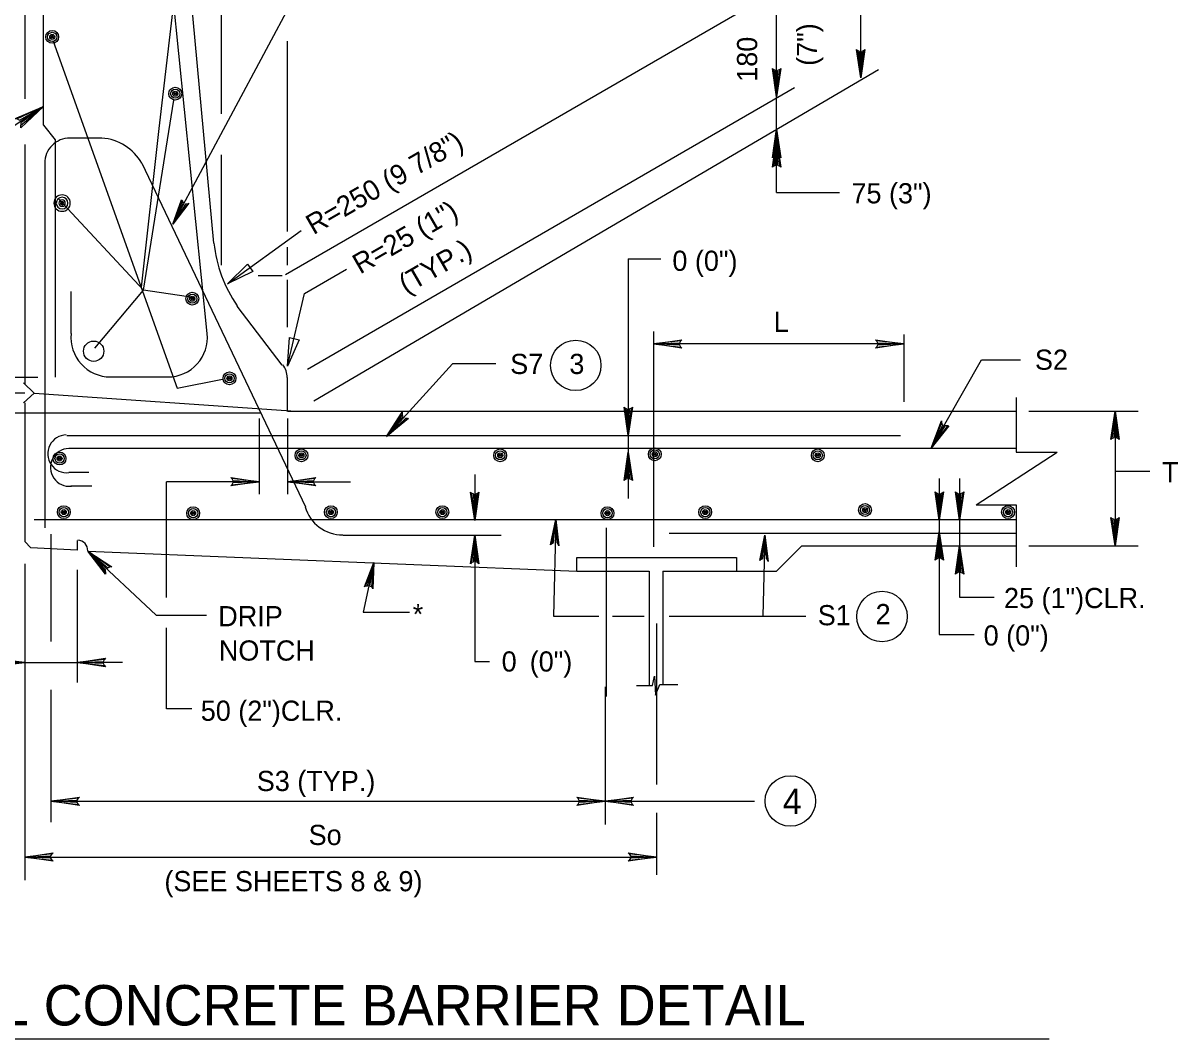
# Model space of a CAD drawing. Extents: x 652000 to 652262, y 303155 to 303399.
# Drawn here: x 652090.8 to 652262.4, y 303155 to 303306 of the extents above; entities that cross this region are included whole.
import ezdxf

# ---------------------------------------------------------------- set-up
doc = ezdxf.new("R2010")
doc.units = 0
doc.layers.add('2', color=7, linetype='Continuous')

msp = doc.modelspace()

# ---------------------------------------------------------------- linework, layer by layer
at = {"layer": '2'}
for p, q in [((652215.29, 303297.83), (652215.29, 303383.14)), ((652120.29, 303292.52), (652120.29, 303373.21)), ((652091.07, 303332.36), (652091.07, 303294.75)), ((652119.19, 303273.3), (652113.72, 303332.21)), ((652093.88, 303290.8), (652093.88, 303328.46)), ((652118.18, 303259.85), (652111.22, 303328.77)), ((652111.07, 303290.33), (652114.82, 303322.36)), ((652113.1, 303276.11), (652133.25, 303313.77)), ((652129.82, 303268.61), (652205.44, 303312.36)), ((652202.79, 303295.02), (652202.79, 303310.8)), ((652095.29, 303303.3), (652113.72, 303251.74)), ((652130.13, 303275.02), (652130.13, 303303.3)), ((652134.04, 303249.86), (652217.94, 303299.08)), ((652133.1, 303254.55), (652205.44, 303296.42)), ((652108.72, 303266.27), (652113.25, 303294.55)), ((652202.79, 303290.2), (652202.79, 303295.02)), ((652093.88, 303293.61), (652084.19, 303287.21)), ((652093.88, 303290.8), (652095.6, 303288.61)), ((652108.41, 303266.74), (652111.07, 303290.33)), ((652202.79, 303280.8), (652202.79, 303290.2)), ((652095.6, 303288.61), (652095.6, 303253.36)), ((652102.54, 303288.9), (652097.79, 303288.9)), ((652091.07, 303287.93), (652091.07, 303284.39)), ((652094.04, 303285.15), (652094.04, 303230.96)), ((652108.48, 303285.15), (652132.79, 303234.08)), ((652120.29, 303270.02), (652120.29, 303286.42)), ((652091.07, 303284.39), (652091.07, 303252.36)), ((652202.79, 303280.8), (652212.16, 303280.8)), ((652108.72, 303266.27), (652096.07, 303279.86)), ((652121.22, 303267.21), (652132.16, 303275.17)), ((652130.13, 303270.02), (652130.13, 303272.67)), ((652180.75, 303270.96), (652185.6, 303270.96)), ((652180.75, 303270.96), (652180.75, 303244.71)), ((652125.75, 303268.46), (652129.35, 303268.46)), ((652132.63, 303265.8), (652138.88, 303269.39)), ((652101.47, 303257.66), (652108.72, 303266.27)), ((652116.38, 303265.17), (652108.72, 303266.27)), ((652130.13, 303260.8), (652130.13, 303267.83)), ((652097.97, 303259.85), (652097.97, 303266.1)), ((652130.13, 303255.02), (652132.63, 303265.8)), ((652129.35, 303255.17), (652122.63, 303263.92)), ((652184.5, 303260.17), (652184.5, 303228.14)), ((652221.69, 303259.71), (652221.69, 303249.71)), ((652221.69, 303258.3), (652184.5, 303258.3)), ((652225.75, 303242.83), (652233.25, 303255.96)), ((652233.25, 303255.96), (652239.04, 303255.96)), ((652154.66, 303255.33), (652144.82, 303244.55)), ((652161.07, 303255.33), (652154.66, 303255.33)), ((652093.02, 303253.3), (652085.44, 303253.3)), ((652090.91, 303252.52), (652092.47, 303250.96)), ((652112.32, 303253.38), (652103.72, 303253.38)), ((652113.72, 303251.74), (652120.45, 303253.07)), ((652130.13, 303248.3), (652130.13, 303253.3)), ((652130.13, 303248.3), (652130.13, 303252.67)), ((652091.07, 303250.96), (652054.69, 303250.96)), ((652090.91, 303249.55), (652092.47, 303250.96)), ((652092.47, 303250.96), (652131.38, 303248.3)), ((652091.07, 303249.55), (652091.07, 303228.92)), ((652238.41, 303250.33), (652238.41, 303242.21)), ((652126.22, 303247.99), (652088.88, 303247.99)), ((652130.13, 303248.3), (652238.41, 303248.3)), ((652240.29, 303248.3), (652256.54, 303248.3)), ((652253.1, 303248.3), (652253.1, 303228.3)), ((652125.91, 303247.21), (652125.91, 303235.96)), ((652130.13, 303247.21), (652130.13, 303235.96)), ((652097.32, 303244.71), (652221.22, 303244.71)), ((652180.75, 303244.71), (652180.75, 303242.21)), ((652097.63, 303242.83), (652238.41, 303242.83)), ((652180.75, 303242.21), (652180.75, 303235.33)), ((652232.47, 303234.39), (652244.5, 303242.21)), ((652238.41, 303242.21), (652244.5, 303242.21)), ((652097.63, 303239.24), (652100.6, 303239.24)), ((652157.94, 303238.92), (652157.94, 303232.05)), ((652253.1, 303239.39), (652258.25, 303239.39)), ((652097.94, 303237.21), (652101.07, 303237.21)), ((652125.91, 303237.83), (652112.16, 303237.83)), ((652112.16, 303220.64), (652112.16, 303237.83)), ((652130.13, 303237.83), (652139.5, 303237.83)), ((652226.97, 303238.3), (652226.97, 303231.74)), ((652229.99, 303238.3), (652229.99, 303231.74)), ((652232.47, 303234.39), (652238.41, 303234.39)), ((652238.41, 303234.39), (652238.41, 303225.17)), ((652092.5, 303232.21), (652238.41, 303232.21)), ((652169.97, 303232.21), (652169.66, 303217.83)), ((652177.47, 303230.96), (652177.47, 303205.9)), ((652186.85, 303230.17), (652238.41, 303230.17)), ((652226.97, 303231.74), (652226.97, 303230.02)), ((652229.99, 303231.74), (652229.99, 303230.02)), ((652091.07, 303228.92), (652092, 303227.99)), ((652094.97, 303230.02), (652094.97, 303214.08)), ((652098.88, 303229.08), (652098.88, 303227.67)), ((652138.41, 303229.86), (652161.85, 303229.86)), ((652157.94, 303229.86), (652157.94, 303211.11)), ((652201.07, 303229.86), (652200.75, 303217.83)), ((652226.97, 303230.02), (652226.97, 303215.11)), ((652229.99, 303230.02), (652229.99, 303220.67)), ((652253.1, 303229.55), (652253.1, 303229.55)), ((652098.88, 303227.67), (652092, 303227.99)), ((652100.44, 303227.52), (652110.6, 303217.99)), ((652100.44, 303227.52), (652173.1, 303224.55)), ((652202.79, 303224.55), (652206.54, 303228.3)), ((652206.54, 303228.3), (652238.41, 303228.3)), ((652240.29, 303228.3), (652256.54, 303228.3)), ((652091.07, 303225.64), (652091.07, 303178.61)), ((652142.94, 303225.8), (652141.38, 303218.46)), ((652173.1, 303224.55), (652173.1, 303226.58)), ((652173.1, 303226.58), (652196.85, 303226.58)), ((652196.85, 303226.58), (652196.85, 303224.55)), ((652098.88, 303224.71), (652098.88, 303207.99)), ((652173.1, 303224.55), (652183.88, 303224.55)), ((652183.88, 303224.55), (652183.88, 303207.52)), ((652185.91, 303224.55), (652202.79, 303224.55)), ((652185.91, 303224.55), (652185.91, 303207.67)), ((652229.99, 303220.67), (652235.14, 303220.67)), ((652141.38, 303218.46), (652148.25, 303218.46)), ((652110.6, 303217.99), (652118.1, 303217.99)), ((652169.66, 303217.83), (652176.38, 303217.83)), ((652178.41, 303217.83), (652183.1, 303217.83)), ((652184.97, 303216.74), (652184.97, 303192.83)), ((652186.85, 303217.83), (652207.16, 303217.83)), ((652112.16, 303204.08), (652112.16, 303216.11)), ((652226.97, 303215.11), (652232.13, 303215.11)), ((652091.07, 303210.96), (652078.97, 303210.96)), ((652091.07, 303210.96), (652098.88, 303210.96)), ((652105.6, 303210.96), (652098.88, 303210.96)), ((652157.94, 303211.11), (652160.13, 303211.11)), ((652184.35, 303207.52), (652184.66, 303208.92)), ((652184.66, 303208.92), (652184.82, 303206.11)), ((652094.97, 303206.89), (652094.97, 303187.21)), ((652177.32, 303207.36), (652177.32, 303186.89)), ((652182, 303207.52), (652184.35, 303207.52)), ((652184.82, 303206.11), (652185.44, 303207.67)), ((652185.44, 303207.67), (652188.1, 303207.67)), ((652115.91, 303204.08), (652112.16, 303204.08)), ((652094.97, 303190.33), (652177.32, 303190.33)), ((652177.32, 303190.33), (652199.5, 303190.33)), ((652184.97, 303188.61), (652184.97, 303179.39)), ((652091.07, 303182.05), (652184.97, 303182.05)), ((652057.09, 303155.02), (652243.28, 303155.02))]:
    msp.add_line(p, q, dxfattribs=at)
for points in [[(652215.75, 303301.89), (652215.44, 303301.74), (652215.29, 303297.83), (652215.75, 303301.89), (652215.91, 303302.05), (652215.29, 303297.83), (652215.13, 303301.74), (652214.82, 303301.89), (652215.29, 303297.83), (652214.66, 303302.05), (652214.82, 303301.89)], [(652203.25, 303299.08), (652202.94, 303298.92), (652202.79, 303295.02), (652203.25, 303299.08), (652203.41, 303299.24), (652202.79, 303295.02), (652202.63, 303298.92), (652202.32, 303299.08), (652202.79, 303295.02), (652202.16, 303299.24), (652202.32, 303299.08)], [(652203.25, 303299.08), (652202.94, 303298.92), (652202.79, 303295.02), (652203.25, 303299.08), (652203.41, 303299.24), (652202.79, 303295.02), (652202.63, 303298.92), (652202.32, 303299.08), (652202.79, 303295.02), (652202.16, 303299.24), (652202.32, 303299.08)], [(652089.94, 303291.74), (652090.32, 303291.55), (652093.88, 303293.61), (652089.94, 303291.74), (652089.57, 303291.74), (652093.88, 303293.61), (652090.5, 303291.17), (652090.5, 303290.8), (652093.88, 303293.61), (652090.5, 303290.42), (652090.5, 303290.8)], [(652202.32, 303286.14), (652202.63, 303286.29), (652202.79, 303290.2), (652202.32, 303286.14), (652202.16, 303285.98), (652202.79, 303290.2), (652202.94, 303286.29), (652203.25, 303286.14), (652202.79, 303290.2), (652203.41, 303285.98), (652203.25, 303286.14)], [(652202.32, 303284.71), (652202.63, 303284.86), (652202.79, 303288.77), (652202.32, 303284.71), (652202.16, 303284.55), (652202.79, 303288.77), (652202.94, 303284.86), (652203.25, 303284.71), (652202.79, 303288.77), (652203.41, 303284.55), (652203.25, 303284.71)], [(652115.29, 303279.08), (652114.97, 303279.08), (652113.1, 303276.11), (652115.29, 303279.08), (652115.44, 303279.24), (652113.1, 303276.11), (652114.66, 303279.24), (652114.5, 303279.55), (652113.1, 303276.11), (652114.35, 303279.71), (652114.5, 303279.55)], [(652188.57, 303257.83), (652188.41, 303258.14), (652184.5, 303258.3), (652188.57, 303257.83), (652188.72, 303257.67), (652184.5, 303258.3), (652188.41, 303258.46), (652188.57, 303258.77), (652184.5, 303258.3), (652188.72, 303258.92), (652188.57, 303258.77)], [(652188.57, 303257.83), (652188.41, 303258.14), (652184.5, 303258.3), (652188.57, 303257.83), (652188.72, 303257.67), (652184.5, 303258.3), (652188.41, 303258.46), (652188.57, 303258.77), (652184.5, 303258.3), (652188.72, 303258.92), (652188.57, 303258.77)], [(652217.63, 303258.77), (652217.79, 303258.46), (652221.69, 303258.3), (652217.63, 303258.77), (652217.47, 303258.92), (652221.69, 303258.3), (652217.79, 303258.14), (652217.63, 303257.83), (652221.69, 303258.3), (652217.47, 303257.67), (652217.63, 303257.83)], [(652147.94, 303247.21), (652147.63, 303247.21), (652144.82, 303244.55), (652147.94, 303247.21), (652148.1, 303247.21), (652144.82, 303244.55), (652147.32, 303247.52), (652147.16, 303247.83), (652144.82, 303244.55), (652147.16, 303248.14), (652147.16, 303247.83)], [(652181.22, 303248.77), (652180.91, 303248.61), (652180.75, 303244.71), (652181.22, 303248.77), (652181.38, 303248.92), (652180.75, 303244.71), (652180.6, 303248.61), (652180.29, 303248.77), (652180.75, 303244.71), (652180.13, 303248.92), (652180.29, 303248.77)], [(652252.63, 303244.24), (652252.94, 303244.39), (652253.1, 303248.3), (652252.63, 303244.24), (652252.47, 303244.08), (652253.1, 303248.3), (652253.25, 303244.39), (652253.57, 303244.24), (652253.1, 303248.3), (652253.72, 303244.08), (652253.57, 303244.24)], [(652252.63, 303244.24), (652252.94, 303244.39), (652253.1, 303248.3), (652252.63, 303244.24), (652252.47, 303244.08), (652253.1, 303248.3), (652253.25, 303244.39), (652253.57, 303244.24), (652253.1, 303248.3), (652253.72, 303244.08), (652253.57, 303244.24)], [(652228.25, 303246.11), (652227.79, 303246.11), (652225.75, 303242.83), (652228.25, 303246.11), (652228.41, 303246.11), (652225.75, 303242.83), (652227.47, 303246.27), (652227.32, 303246.58), (652225.75, 303242.83), (652227.32, 303246.89), (652227.32, 303246.58)], [(652180.29, 303238.14), (652180.6, 303238.3), (652180.75, 303242.21), (652180.29, 303238.14), (652180.13, 303237.99), (652180.75, 303242.21), (652180.91, 303238.3), (652181.22, 303238.14), (652180.75, 303242.21), (652181.38, 303237.99), (652181.22, 303238.14)], [(652121.85, 303238.3), (652122, 303237.99), (652125.91, 303237.83), (652121.85, 303238.3), (652121.69, 303238.46), (652125.91, 303237.83), (652122, 303237.67), (652121.85, 303237.36), (652125.91, 303237.83), (652121.69, 303237.21), (652121.85, 303237.36)], [(652134.19, 303237.36), (652134.04, 303237.67), (652130.13, 303237.83), (652134.19, 303237.36), (652134.35, 303237.21), (652130.13, 303237.83), (652134.04, 303237.99), (652134.19, 303238.3), (652130.13, 303237.83), (652134.35, 303238.46), (652134.19, 303238.3)], [(652158.41, 303236.11), (652158.1, 303235.96), (652157.94, 303232.05), (652158.41, 303236.11), (652158.57, 303236.27), (652157.94, 303232.05), (652157.79, 303235.96), (652157.47, 303236.11), (652157.94, 303232.05), (652157.32, 303236.27), (652157.47, 303236.11)], [(652227.44, 303236.17), (652227.13, 303236.01), (652226.97, 303232.1), (652227.44, 303236.17), (652227.6, 303236.32), (652226.97, 303232.1), (652226.82, 303236.01), (652226.51, 303236.17), (652226.97, 303232.1), (652226.35, 303236.32), (652226.51, 303236.17)], [(652230.46, 303236.17), (652230.14, 303236.01), (652229.99, 303232.1), (652230.46, 303236.17), (652230.61, 303236.32), (652229.99, 303232.1), (652229.83, 303236.01), (652229.52, 303236.17), (652229.99, 303232.1), (652229.36, 303236.32), (652229.52, 303236.17)], [(652169.35, 303228.61), (652169.66, 303228.77), (652169.97, 303232.21), (652169.35, 303228.61), (652169.19, 303228.46), (652169.97, 303232.21), (652170.13, 303228.77), (652170.29, 303228.61), (652169.97, 303232.21), (652170.44, 303228.3), (652170.29, 303228.61)], [(652253.57, 303232.36), (652253.25, 303232.21), (652253.1, 303228.3), (652253.57, 303232.36), (652253.72, 303232.52), (652253.1, 303228.3), (652252.94, 303232.21), (652252.63, 303232.36), (652253.1, 303228.3), (652252.47, 303232.52), (652252.63, 303232.36)], [(652226.51, 303226.32), (652226.82, 303226.48), (652226.97, 303230.38), (652226.51, 303226.32), (652226.35, 303226.17), (652226.97, 303230.38), (652227.13, 303226.48), (652227.44, 303226.32), (652226.97, 303230.38), (652227.6, 303226.17), (652227.44, 303226.32)], [(652157.47, 303225.8), (652157.79, 303225.96), (652157.94, 303229.86), (652157.47, 303225.8), (652157.32, 303225.64), (652157.94, 303229.86), (652158.1, 303225.96), (652158.41, 303225.8), (652157.94, 303229.86), (652158.57, 303225.64), (652158.41, 303225.8)], [(652200.44, 303226.27), (652200.75, 303226.42), (652201.07, 303229.86), (652200.44, 303226.27), (652200.29, 303226.11), (652201.07, 303229.86), (652201.22, 303226.42), (652201.38, 303226.27), (652201.07, 303229.86), (652201.54, 303225.96), (652201.38, 303226.27)], [(652103.1, 303224.39), (652103.1, 303224.71), (652100.44, 303227.52), (652103.1, 303224.39), (652103.1, 303224.08), (652100.44, 303227.52), (652103.41, 303225.02), (652103.72, 303225.17), (652100.44, 303227.52), (652104.04, 303225.17), (652103.72, 303225.17)], [(652229.52, 303224.24), (652229.83, 303224.39), (652229.99, 303228.3), (652229.52, 303224.24), (652229.36, 303224.08), (652229.99, 303228.3), (652230.14, 303224.39), (652230.46, 303224.24), (652229.99, 303228.3), (652230.61, 303224.08), (652230.46, 303224.24)], [(652141.69, 303222.36), (652142, 303222.36), (652142.94, 303225.8), (652141.69, 303222.36), (652141.54, 303222.21), (652142.94, 303225.8), (652142.32, 303222.36), (652142.63, 303222.21), (652142.94, 303225.8), (652142.79, 303221.89), (652142.63, 303222.21)], [(652087, 303211.42), (652087.16, 303211.11), (652091.07, 303210.96), (652087, 303211.42), (652086.85, 303211.58), (652091.07, 303210.96), (652087.16, 303210.8), (652087, 303210.49), (652091.07, 303210.96), (652086.85, 303210.33), (652087, 303210.49)], [(652102.94, 303210.49), (652102.79, 303210.8), (652098.88, 303210.96), (652102.94, 303210.49), (652103.1, 303210.33), (652098.88, 303210.96), (652102.79, 303211.11), (652102.94, 303211.42), (652098.88, 303210.96), (652103.1, 303211.58), (652102.94, 303211.42)], [(652099.04, 303189.86), (652098.88, 303190.17), (652094.97, 303190.33), (652099.04, 303189.86), (652099.19, 303189.71), (652094.97, 303190.33), (652098.88, 303190.49), (652099.04, 303190.8), (652094.97, 303190.33), (652099.19, 303190.96), (652099.04, 303190.8)], [(652099.04, 303189.86), (652098.88, 303190.17), (652094.97, 303190.33), (652099.04, 303189.86), (652099.19, 303189.71), (652094.97, 303190.33), (652098.88, 303190.49), (652099.04, 303190.8), (652094.97, 303190.33), (652099.19, 303190.96), (652099.04, 303190.8)], [(652173.25, 303190.8), (652173.41, 303190.49), (652177.32, 303190.33), (652173.25, 303190.8), (652173.1, 303190.96), (652177.32, 303190.33), (652173.41, 303190.17), (652173.25, 303189.86), (652177.32, 303190.33), (652173.1, 303189.71), (652173.25, 303189.86)], [(652173.25, 303190.8), (652173.41, 303190.49), (652177.32, 303190.33), (652173.25, 303190.8), (652173.1, 303190.96), (652177.32, 303190.33), (652173.41, 303190.17), (652173.25, 303189.86), (652177.32, 303190.33), (652173.1, 303189.71), (652173.25, 303189.86)], [(652181.38, 303189.86), (652181.22, 303190.17), (652177.32, 303190.33), (652181.38, 303189.86), (652181.54, 303189.71), (652177.32, 303190.33), (652181.22, 303190.49), (652181.38, 303190.8), (652177.32, 303190.33), (652181.54, 303190.96), (652181.38, 303190.8)], [(652095.13, 303181.58), (652094.97, 303181.89), (652091.07, 303182.05), (652095.13, 303181.58), (652095.29, 303181.42), (652091.07, 303182.05), (652094.97, 303182.21), (652095.13, 303182.52), (652091.07, 303182.05), (652095.29, 303182.67), (652095.13, 303182.52)], [(652180.91, 303182.52), (652181.07, 303182.21), (652184.97, 303182.05), (652180.91, 303182.52), (652180.75, 303182.67), (652184.97, 303182.05), (652181.07, 303181.89), (652180.91, 303181.58), (652184.97, 303182.05), (652180.75, 303181.42), (652180.91, 303181.58)]]:
    msp.add_lwpolyline(points, dxfattribs=at)
for points in [[(652124.97, 303269.08), (652121.22, 303267.21), (652124.19, 303270.17)], [(652131.85, 303258.92), (652130.13, 303255.02), (652130.44, 303259.24)]]:
    msp.add_lwpolyline(points, close=True, dxfattribs=at)
for centre, radius in [((652095.16, 303303.93), 0.954), ((652095.16, 303303.93), 0.681), ((652095.16, 303303.93), 0.372), ((652095.16, 303303.93), 0.188), ((652095.16, 303303.93), 0.0805), ((652113.44, 303295.49), 0.954), ((652113.44, 303295.49), 0.681), ((652113.44, 303295.49), 0.372), ((652113.44, 303295.49), 0.188), ((652113.44, 303295.49), 0.0805), ((652115.97, 303265.02), 0.954), ((652115.97, 303265.02), 0.681), ((652115.97, 303265.02), 0.372), ((652115.97, 303265.02), 0.188), ((652115.97, 303265.02), 0.0805), ((652101.32, 303257.22), 1.51), ((652172.95, 303255.11), 3.75), ((652121.5, 303253.19), 0.954), ((652121.5, 303253.19), 0.681), ((652121.5, 303253.19), 0.372), ((652121.5, 303253.19), 0.188), ((652121.5, 303253.19), 0.0805), ((652096.25, 303241.27), 0.954), ((652132.19, 303241.74), 0.954), ((652132.19, 303241.74), 0.681), ((652161.72, 303241.74), 0.954), ((652161.72, 303241.74), 0.681), ((652184.69, 303241.9), 0.954), ((652184.69, 303241.9), 0.681), ((652184.69, 303241.9), 0.372), ((652208.91, 303241.74), 0.954), ((652208.91, 303241.74), 0.681), ((652096.25, 303241.27), 0.681), ((652096.25, 303241.27), 0.372), ((652096.25, 303241.27), 0.188), ((652096.25, 303241.27), 0.0805), ((652132.19, 303241.74), 0.372), ((652132.19, 303241.74), 0.188), ((652132.19, 303241.74), 0.0805), ((652161.72, 303241.74), 0.372), ((652161.72, 303241.74), 0.188), ((652161.72, 303241.74), 0.0805), ((652184.69, 303241.9), 0.188), ((652184.69, 303241.9), 0.0805), ((652208.91, 303241.74), 0.372), ((652208.91, 303241.74), 0.188), ((652208.91, 303241.74), 0.0805), ((652096.88, 303233.3), 0.954), ((652096.88, 303233.3), 0.681), ((652096.88, 303233.3), 0.372), ((652116.1, 303233.15), 0.954), ((652116.1, 303233.15), 0.681), ((652136.57, 303233.3), 0.954), ((652136.57, 303233.3), 0.681), ((652136.57, 303233.3), 0.372), ((652153.13, 303233.3), 0.954), ((652153.13, 303233.3), 0.681), ((652153.13, 303233.3), 0.372), ((652177.66, 303233.15), 0.954), ((652177.66, 303233.15), 0.681), ((652192.19, 303233.3), 0.954), ((652192.19, 303233.3), 0.681), ((652192.19, 303233.3), 0.372), ((652215.94, 303233.61), 0.954), ((652215.94, 303233.61), 0.681), ((652215.94, 303233.61), 0.372), ((652215.94, 303233.61), 0.188), ((652215.94, 303233.61), 0.0805), ((652237.19, 303233.3), 0.954), ((652237.19, 303233.3), 0.681), ((652237.19, 303233.3), 0.372), ((652096.88, 303233.3), 0.188), ((652096.88, 303233.3), 0.0805), ((652116.1, 303233.15), 0.372), ((652116.1, 303233.15), 0.188), ((652116.1, 303233.15), 0.0805), ((652136.57, 303233.3), 0.188), ((652136.57, 303233.3), 0.0805), ((652153.13, 303233.3), 0.188), ((652153.13, 303233.3), 0.0805), ((652177.66, 303233.15), 0.372), ((652177.66, 303233.15), 0.188), ((652177.66, 303233.15), 0.0805), ((652192.19, 303233.3), 0.188), ((652192.19, 303233.3), 0.0805), ((652237.19, 303233.3), 0.188), ((652237.19, 303233.3), 0.0805), ((652218.46, 303217.79), 3.75), ((652204.84, 303190.37), 3.75)]:
    msp.add_circle(centre, radius, dxfattribs=at)
for centre, radius, start, end in [((652097.79, 303285.15), 3.75, 90, 180.0003), ((652102.02, 303281.51), 7.4, 29.3924, 85.9732), ((652096.63, 303279.23), 1.22, 0, 180), ((652096.63, 303279.23), 0.873, 0, 180), ((652096.63, 303279.23), 1.22, 180, 0), ((652096.63, 303279.23), 0.873, 180, 0), ((652096.63, 303279.23), 0.478, 0, 180), ((652096.63, 303279.23), 0.478, 180, 0), ((652096.63, 303279.23), 0.241, 0, 180), ((652096.63, 303279.23), 0.241, 180, 0), ((652096.63, 303279.23), 0.103, 0, 180), ((652096.63, 303279.23), 0.103, 180, 0), ((652138.91, 303275.36), 19.84, 186.0098, 214.992), ((652103.79, 303259.25), 5.85, 174.1623, 270), ((652112.36, 303259.25), 5.85, 270, 5.8377), ((652126.95, 303253.29), 3.12, 0, 37.624), ((652097.31, 303241.97), 2.81, 91.1842, 276.3835), ((652097.7, 303239.95), 2.81, 91.2481, 276.3117), ((652138.35, 303235.77), 5.86, 196.5463, 270), ((652098.95, 303227.63), 1.49, 356.2804, 89.6526)]:
    msp.add_arc(centre, radius, start, end, dxfattribs=at)

# ---------------------------------------------------------------- texts
for s, rotation, p in [('(7")', 90, (652208.82, 303299.63)), ('180', 90, (652199.91, 303297.26)), ('R=250 (9 7/8")', 30, (652133.98, 303274.45)), ('R=25 (1")', 30, (652140.91, 303268.6)), ('(TYP.)', 30, (652147.77, 303265.64))]:
    msp.add_text(s, height=3, rotation=rotation, dxfattribs=at).set_placement(p)
for s, height, p in [('75 (3")', 3, (652213.92, 303279.19)), ('0 (0")', 3, (652187.31, 303269.16)), ('L', 3, (652202.37, 303260.08)), ('S7', 3, (652163.21, 303253.83)), ('3', 3, (652172, 303253.83)), ('S2', 3, (652241.18, 303254.46)), ('T', 3, (652260.06, 303237.74)), ('25 (1")CLR.', 3, (652236.58, 303219.04)), ('DRIP', 3, (652119.83, 303216.34)), ('*', 3, (652148.73, 303216.64)), ('S1', 3, (652208.91, 303216.49)), ('2', 3, (652217.5, 303216.65)), ('0 (0")', 3, (652233.56, 303213.48)), ('NOTCH', 3, (652119.92, 303211.24)), ('0', 3, (652161.94, 303209.61)), ('(0")', 3, (652166.11, 303209.61)), ('50 (2")CLR.', 3, (652117.23, 303202.29)), (' S3 (TYP.)', 3, (652124.44, 303191.85)), ('4', 3.75, (652203.72, 303188.46)), ('So', 3, (652133.26, 303183.83)), ('(SEE SHEETS 8 & 9)', 3, (652111.83, 303176.96)), ('TYPICAL CONCRETE BARRIER DETAIL', 6, (652058.22, 303157.02))]:
    msp.add_text(s, height=height, dxfattribs=at).set_placement(p)

doc.saveas('drawing.dxf')
